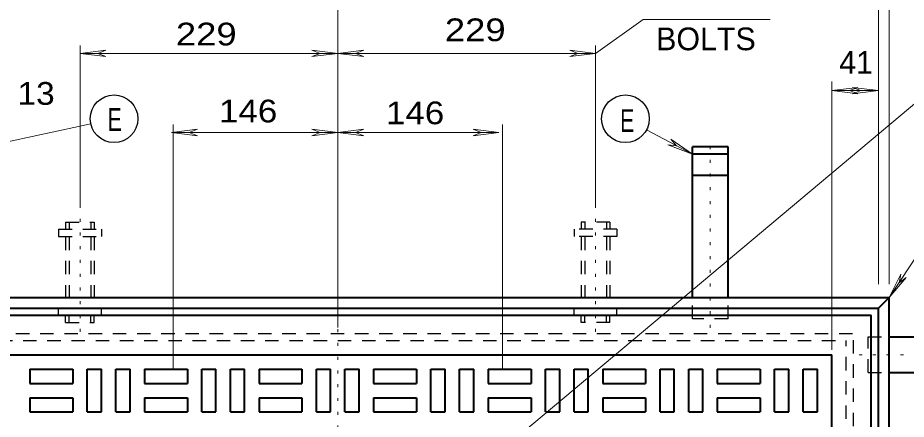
# Model space of a CAD drawing. Extents: x 312583 to 312854, y 144419 to 144597.
# Drawn here: x 312653.44 to 312683.17, y 144508.06 to 144521.49 of the extents above; entities that cross this region are included whole.
import ezdxf

# ---------------------------------------------------------------- set-up
doc = ezdxf.new("R2010")
doc.units = 0
doc.header["$LTSCALE"] = 0.3
doc.linetypes.add('DOTTED', pattern=[1.5, 0.3, -1.2])
doc.linetypes.add('SHORT_DASHED', pattern=[2.7, 1.5, -1.2])
doc.layers.add('1', color=7, linetype='Continuous', lineweight=13)

msp = doc.modelspace()

# ---------------------------------------------------------------- linework, layer by layer
at = {"layer": '1'}
for p, q in [((312682.5955, 144512.5763), (312682.5955, 144528.8066)), ((312682.2351, 144512.5763), (312682.2351, 144526.6523)), ((312664.1495, 144511.1273), (312664.1495, 144524.3063)), ((312655.5245, 144515.229), (312655.5245, 144520.565)), ((312655.5245, 144520.2966), (312656.3908, 144520.404)), ((312656.3908, 144520.404), (312656.1148, 144520.2966)), ((312663.2831, 144520.404), (312663.5591, 144520.2966)), ((312664.1495, 144520.2966), (312663.2831, 144520.404)), ((312664.1495, 144520.2966), (312665.0158, 144520.404)), ((312665.0158, 144520.404), (312664.7398, 144520.2966)), ((312671.9081, 144520.404), (312672.1841, 144520.2966)), ((312672.7745, 144520.2966), (312671.9081, 144520.404)), ((312672.7745, 144515.229), (312672.7745, 144520.565)), ((312655.5245, 144520.2966), (312664.1495, 144520.2966)), ((312655.5245, 144520.2966), (312656.3908, 144520.1893)), ((312656.3908, 144520.1893), (312656.1148, 144520.2966)), ((312663.2831, 144520.1893), (312663.5591, 144520.2966)), ((312664.1495, 144520.2966), (312663.2831, 144520.1893)), ((312672.7745, 144520.2966), (312664.1495, 144520.2966)), ((312664.1495, 144520.2966), (312665.0158, 144520.1893)), ((312665.0158, 144520.1893), (312664.7398, 144520.2966)), ((312671.9081, 144520.1893), (312672.1841, 144520.2966)), ((312672.7745, 144520.2966), (312671.9081, 144520.1893)), ((312680.6788, 144510.3836), (312680.6788, 144519.3536)), ((312680.6788, 144519.0546), (312681.5451, 144519.162)), ((312680.6788, 144519.0546), (312682.2351, 144519.0546)), ((312680.6788, 144519.0546), (312681.5451, 144518.9473)), ((312681.5451, 144519.162), (312681.2691, 144519.0546)), ((312681.5451, 144518.9473), (312681.2691, 144519.0546)), ((312681.3688, 144519.162), (312681.6448, 144519.0546)), ((312682.2351, 144519.0546), (312681.3688, 144519.162)), ((312681.3688, 144518.9473), (312681.6448, 144519.0546)), ((312682.2351, 144519.0546), (312681.3688, 144518.9473)), ((312655.8848, 144517.943), (312652.2891, 144517.1686)), ((312658.5835, 144517.6516), (312659.4498, 144517.759)), ((312658.6371, 144509.7166), (312658.6371, 144517.92)), ((312659.4498, 144517.759), (312659.1738, 144517.6516)), ((312663.2831, 144517.759), (312663.5591, 144517.6516)), ((312664.1495, 144517.6516), (312663.2831, 144517.759)), ((312664.1495, 144517.6516), (312665.0158, 144517.759)), ((312665.0158, 144517.759), (312664.7398, 144517.6516)), ((312668.6728, 144517.759), (312668.9488, 144517.6516)), ((312669.5391, 144517.6516), (312668.6728, 144517.759)), ((312669.6541, 144509.7166), (312669.6541, 144517.92)), ((312674.4765, 144517.736), (312676.0098, 144516.931)), ((312658.5835, 144517.6516), (312659.4498, 144517.5443)), ((312659.4498, 144517.5443), (312659.1738, 144517.6516)), ((312663.2831, 144517.5443), (312663.5591, 144517.6516)), ((312664.1495, 144517.6516), (312663.2831, 144517.5443)), ((312664.1495, 144517.6516), (312665.0158, 144517.5443)), ((312665.0158, 144517.5443), (312664.7398, 144517.6516)), ((312668.6728, 144517.5443), (312668.9488, 144517.6516)), ((312669.5391, 144517.6516), (312668.6728, 144517.5443)), ((312675.2891, 144517.4293), (312675.4808, 144517.207)), ((312676.0098, 144516.931), (312675.2891, 144517.4293)), ((312675.1895, 144517.2376), (312675.4808, 144517.207)), ((312676.0098, 144516.931), (312675.1895, 144517.2376)), ((312682.5955, 144512.1393), (312682.9865, 144512.9136)), ((312682.5955, 144512.1393), (312683.1628, 144512.7986)), ((312682.9865, 144512.9136), (312682.9251, 144512.63)), ((312683.1628, 144512.7986), (312682.9251, 144512.63))]:
    msp.add_line(p, q, dxfattribs=at)
at = {"layer": '1', "linetype": 'DOTTED'}
for p, q in [((312676.6078, 144511.1196), (312676.6078, 144517.5213)), ((312655.5245, 144515.229), (312655.5245, 144510.744)), ((312672.7745, 144515.229), (312672.7745, 144510.744)), ((312664.1495, 144507.294), (312664.1495, 144514.9606)), ((312681.5911, 144510.2226), (312687.9851, 144510.2226))]:
    msp.add_line(p, q, dxfattribs=at)
at = {"layer": '1', "lineweight": 40}
for p, q in [((312677.2058, 144517.1686), (312676.0098, 144517.1686)), ((312676.0098, 144512.1393), (312676.0098, 144517.1686)), ((312677.2058, 144512.1393), (312677.2058, 144517.1686)), ((312677.2058, 144516.931), (312676.0098, 144516.931)), ((312677.2058, 144516.2103), (312676.0098, 144516.2103)), ((312645.6958, 144512.1393), (312682.5955, 144512.1393)), ((312682.2351, 144511.779), (312682.5955, 144512.1393)), ((312682.5955, 144500.1563), (312682.5955, 144512.1393)), ((312646.0561, 144511.779), (312682.2351, 144511.779)), ((312682.2351, 144500.5166), (312682.2351, 144511.779)), ((312681.9975, 144500.7543), (312681.9975, 144511.5413)), ((312682.6108, 144510.8206), (312687.6401, 144510.8206)), ((312647.6125, 144510.2226), (312680.6788, 144510.2226)), ((312680.6788, 144502.073), (312680.6788, 144510.2226)), ((312653.8455, 144509.7396), (312655.2791, 144509.7396)), ((312653.8455, 144509.7396), (312653.8455, 144509.2643)), ((312655.2791, 144509.7396), (312655.2791, 144509.2643)), ((312655.7621, 144508.306), (312655.7621, 144509.7396)), ((312655.7621, 144509.7396), (312656.2375, 144509.7396)), ((312656.2375, 144508.306), (312656.2375, 144509.7396)), ((312656.7205, 144508.306), (312656.7205, 144509.7396)), ((312656.7205, 144509.7396), (312657.1958, 144509.7396)), ((312657.1958, 144508.306), (312657.1958, 144509.7396)), ((312657.6788, 144509.7396), (312659.1125, 144509.7396)), ((312657.6788, 144509.7396), (312657.6788, 144509.2643)), ((312659.1125, 144509.7396), (312659.1125, 144509.2643)), ((312659.5955, 144508.306), (312659.5955, 144509.7396)), ((312659.5955, 144509.7396), (312660.0708, 144509.7396)), ((312660.0708, 144508.306), (312660.0708, 144509.7396)), ((312660.5538, 144508.306), (312660.5538, 144509.7396)), ((312660.5538, 144509.7396), (312661.0291, 144509.7396)), ((312661.0291, 144508.306), (312661.0291, 144509.7396)), ((312661.5121, 144509.7396), (312662.9458, 144509.7396)), ((312661.5121, 144509.7396), (312661.5121, 144509.2643)), ((312662.9458, 144509.7396), (312662.9458, 144509.2643)), ((312663.4288, 144508.306), (312663.4288, 144509.7396)), ((312663.4288, 144509.7396), (312663.9041, 144509.7396)), ((312663.9041, 144508.306), (312663.9041, 144509.7396)), ((312664.3871, 144508.306), (312664.3871, 144509.7396)), ((312664.3871, 144509.7396), (312664.8625, 144509.7396)), ((312664.8625, 144508.306), (312664.8625, 144509.7396)), ((312665.3455, 144509.7396), (312666.7791, 144509.7396)), ((312665.3455, 144509.7396), (312665.3455, 144509.2643)), ((312666.7791, 144509.7396), (312666.7791, 144509.2643)), ((312667.2621, 144508.306), (312667.2621, 144509.7396)), ((312667.2621, 144509.7396), (312667.7375, 144509.7396)), ((312667.7375, 144508.306), (312667.7375, 144509.7396)), ((312668.2205, 144508.306), (312668.2205, 144509.7396)), ((312668.2205, 144509.7396), (312668.6958, 144509.7396)), ((312668.6958, 144508.306), (312668.6958, 144509.7396)), ((312669.1788, 144509.7396), (312670.6125, 144509.7396)), ((312669.1788, 144509.7396), (312669.1788, 144509.2643)), ((312670.6125, 144509.7396), (312670.6125, 144509.2643)), ((312671.0955, 144508.306), (312671.0955, 144509.7396)), ((312671.0955, 144509.7396), (312671.5708, 144509.7396)), ((312671.5708, 144508.306), (312671.5708, 144509.7396)), ((312672.0538, 144508.306), (312672.0538, 144509.7396)), ((312672.0538, 144509.7396), (312672.5291, 144509.7396)), ((312672.5291, 144508.306), (312672.5291, 144509.7396)), ((312673.0121, 144509.7396), (312674.4458, 144509.7396)), ((312673.0121, 144509.7396), (312673.0121, 144509.2643)), ((312674.4458, 144509.7396), (312674.4458, 144509.2643)), ((312674.9288, 144508.306), (312674.9288, 144509.7396)), ((312674.9288, 144509.7396), (312675.4041, 144509.7396)), ((312675.4041, 144508.306), (312675.4041, 144509.7396)), ((312675.8871, 144508.306), (312675.8871, 144509.7396)), ((312675.8871, 144509.7396), (312676.3625, 144509.7396)), ((312676.3625, 144508.306), (312676.3625, 144509.7396)), ((312676.8455, 144509.7396), (312678.2791, 144509.7396)), ((312676.8455, 144509.7396), (312676.8455, 144509.2643)), ((312678.2791, 144509.7396), (312678.2791, 144509.2643)), ((312678.7621, 144508.306), (312678.7621, 144509.7396)), ((312678.7621, 144509.7396), (312679.2375, 144509.7396)), ((312679.2375, 144508.306), (312679.2375, 144509.7396)), ((312679.7205, 144508.306), (312679.7205, 144509.7396)), ((312679.7205, 144509.7396), (312680.1958, 144509.7396)), ((312680.1958, 144508.306), (312680.1958, 144509.7396)), ((312682.6108, 144509.6246), (312687.6401, 144509.6246)), ((312653.8455, 144509.2643), (312655.2791, 144509.2643)), ((312657.6788, 144509.2643), (312659.1125, 144509.2643)), ((312661.5121, 144509.2643), (312662.9458, 144509.2643)), ((312665.3455, 144509.2643), (312666.7791, 144509.2643)), ((312669.1788, 144509.2643), (312670.6125, 144509.2643)), ((312673.0121, 144509.2643), (312674.4458, 144509.2643)), ((312676.8455, 144509.2643), (312678.2791, 144509.2643)), ((312653.8455, 144508.7813), (312655.2791, 144508.7813)), ((312653.8455, 144508.7813), (312653.8455, 144508.306)), ((312655.2791, 144508.7813), (312655.2791, 144508.306)), ((312657.6788, 144508.7813), (312659.1125, 144508.7813)), ((312657.6788, 144508.7813), (312657.6788, 144508.306)), ((312659.1125, 144508.7813), (312659.1125, 144508.306)), ((312661.5121, 144508.7813), (312662.9458, 144508.7813)), ((312661.5121, 144508.7813), (312661.5121, 144508.306)), ((312662.9458, 144508.7813), (312662.9458, 144508.306)), ((312665.3455, 144508.7813), (312666.7791, 144508.7813)), ((312665.3455, 144508.7813), (312665.3455, 144508.306)), ((312666.7791, 144508.7813), (312666.7791, 144508.306)), ((312669.1788, 144508.7813), (312670.6125, 144508.7813)), ((312669.1788, 144508.7813), (312669.1788, 144508.306)), ((312670.6125, 144508.7813), (312670.6125, 144508.306)), ((312673.0121, 144508.7813), (312674.4458, 144508.7813)), ((312673.0121, 144508.7813), (312673.0121, 144508.306)), ((312674.4458, 144508.7813), (312674.4458, 144508.306)), ((312676.8455, 144508.7813), (312678.2791, 144508.7813)), ((312676.8455, 144508.7813), (312676.8455, 144508.306)), ((312678.2791, 144508.7813), (312678.2791, 144508.306)), ((312653.8455, 144508.306), (312655.2791, 144508.306)), ((312655.7621, 144508.306), (312656.2375, 144508.306)), ((312656.7205, 144508.306), (312657.1958, 144508.306)), ((312657.6788, 144508.306), (312659.1125, 144508.306)), ((312659.5955, 144508.306), (312660.0708, 144508.306)), ((312660.5538, 144508.306), (312661.0291, 144508.306)), ((312661.5121, 144508.306), (312662.9458, 144508.306)), ((312663.4288, 144508.306), (312663.9041, 144508.306)), ((312664.3871, 144508.306), (312664.8625, 144508.306)), ((312665.3455, 144508.306), (312666.7791, 144508.306)), ((312667.2621, 144508.306), (312667.7375, 144508.306)), ((312668.2205, 144508.306), (312668.6958, 144508.306)), ((312669.1788, 144508.306), (312670.6125, 144508.306)), ((312671.0955, 144508.306), (312671.5708, 144508.306)), ((312672.0538, 144508.306), (312672.5291, 144508.306)), ((312673.0121, 144508.306), (312674.4458, 144508.306)), ((312674.9288, 144508.306), (312675.4041, 144508.306)), ((312675.8871, 144508.306), (312676.3625, 144508.306)), ((312676.8455, 144508.306), (312678.2791, 144508.306)), ((312678.7621, 144508.306), (312679.2375, 144508.306)), ((312679.7205, 144508.306), (312680.1958, 144508.306))]:
    msp.add_line(p, q, dxfattribs=at)
at = {"layer": '1', "linetype": 'SHORT_DASHED', "lineweight": 25}
for p, q in [((312655.0415, 144514.654), (312655.9998, 144514.654)), ((312655.0415, 144514.654), (312655.0415, 144514.4163)), ((312655.1641, 144514.654), (312655.1641, 144514.4163)), ((312655.8848, 144514.654), (312655.8848, 144514.4163)), ((312655.9998, 144514.654), (312655.9998, 144514.4163)), ((312673.2498, 144514.654), (312672.2915, 144514.654)), ((312672.2915, 144514.654), (312672.2915, 144514.4163)), ((312672.4141, 144514.654), (312672.4141, 144514.4163)), ((312673.1348, 144514.654), (312673.1348, 144514.4163)), ((312673.2498, 144514.654), (312673.2498, 144514.4163)), ((312654.8038, 144514.4163), (312656.2375, 144514.4163)), ((312654.8038, 144514.4163), (312654.8038, 144514.171)), ((312654.8038, 144514.171), (312656.2375, 144514.171)), ((312655.0415, 144514.171), (312655.0415, 144511.779)), ((312655.1641, 144514.171), (312655.1641, 144511.779)), ((312655.8848, 144514.171), (312655.8848, 144511.779)), ((312655.9998, 144514.171), (312655.9998, 144511.779)), ((312656.2375, 144514.4163), (312656.2375, 144514.171)), ((312673.4875, 144514.4163), (312672.0538, 144514.4163)), ((312672.0538, 144514.4163), (312672.0538, 144514.171)), ((312673.4875, 144514.171), (312672.0538, 144514.171)), ((312672.2915, 144514.171), (312672.2915, 144511.779)), ((312672.4141, 144514.171), (312672.4141, 144511.779)), ((312673.1348, 144514.171), (312673.1348, 144511.779)), ((312673.2498, 144514.171), (312673.2498, 144511.779)), ((312673.4875, 144514.4163), (312673.4875, 144514.171)), ((312676.0098, 144511.4186), (312676.0098, 144512.1393)), ((312677.2058, 144511.4186), (312677.2058, 144512.1393)), ((312654.8038, 144511.5413), (312654.8038, 144511.779)), ((312656.2375, 144511.5413), (312656.2375, 144511.779)), ((312672.0538, 144511.5413), (312672.0538, 144511.779)), ((312673.4875, 144511.5413), (312673.4875, 144511.779)), ((312654.8038, 144511.5413), (312656.2375, 144511.5413)), ((312655.0415, 144511.296), (312655.0415, 144511.5413)), ((312655.1641, 144511.296), (312655.1641, 144511.5413)), ((312655.8848, 144511.296), (312655.8848, 144511.5413)), ((312655.9998, 144511.296), (312655.9998, 144511.5413)), ((312673.4875, 144511.5413), (312672.0538, 144511.5413)), ((312672.2915, 144511.296), (312672.2915, 144511.5413)), ((312672.4141, 144511.296), (312672.4141, 144511.5413)), ((312673.1348, 144511.296), (312673.1348, 144511.5413)), ((312673.2498, 144511.296), (312673.2498, 144511.5413)), ((312655.0415, 144511.296), (312655.9998, 144511.296)), ((312673.2498, 144511.296), (312672.2915, 144511.296)), ((312677.2058, 144511.4186), (312676.0098, 144511.4186)), ((312646.8995, 144510.9356), (312681.3995, 144510.9356)), ((312681.3995, 144501.3523), (312681.3995, 144510.9356)), ((312681.1541, 144501.5976), (312681.1541, 144510.698)), ((312681.8901, 144509.6246), (312681.8901, 144510.8206)), ((312681.8901, 144510.8206), (312682.6108, 144510.8206)), ((312681.8901, 144509.6246), (312682.6108, 144509.6246))]:
    msp.add_line(p, q, dxfattribs=at)
at = {"layer": '1'}
for points in [[(312672.7745, 144520.2966), (312674.3615, 144521.4313), (312678.6165, 144521.4313)], [(312669.0408, 144506.535), (312685.9458, 144520.703), (312688.1155, 144520.703)], [(312658.5835, 144517.6516), (312664.1495, 144517.6516), (312669.5391, 144517.6516)], [(312686.9041, 144515.3516), (312684.7345, 144515.3516), (312682.5955, 144512.1393)]]:
    msp.add_lwpolyline(points, dxfattribs=at)
at = {"layer": '1', "lineweight": 40}
msp.add_lwpolyline([(312646.3015, 144500.7543), (312646.3015, 144511.5413), (312681.9975, 144511.5413)], dxfattribs=at)
at = {"layer": '1', "linetype": 'SHORT_DASHED', "lineweight": 25}
msp.add_lwpolyline([(312647.1371, 144501.5976), (312647.1371, 144510.698), (312681.1541, 144510.698)], dxfattribs=at)
at = {"layer": '1', "lineweight": 25}
for centre in [(312656.661, 144518.1116), (312673.7721, 144518.1116)]:
    msp.add_circle(centre, 0.7964, dxfattribs=at)

# ---------------------------------------------------------------- texts
at = {"layer": '1'}
for s, width, p in [('229 ', 1.2, (312658.7287, 144520.564)), ('229 ', 1.2, (312667.729, 144520.7059)), ('13 ', 1.1, (312653.4301, 144518.5783)), ('146 ', 1.15, (312660.1716, 144517.9899)), ('146 ', 1.15, (312665.7578, 144517.9286)), ('E', 0.7, (312656.4454, 144517.7062)), ('E', 0.7, (312673.5928, 144517.6708))]:
    msp.add_text(s, height=0.76, dxfattribs=dict(at, width=width)).set_placement(p)
for s, p in [('BOLTS', (312674.7985, 144520.403)), ('41 ', (312680.9227, 144519.6162))]:
    msp.add_text(s, height=0.76, dxfattribs=at).set_placement(p)

doc.saveas('drawing.dxf')
